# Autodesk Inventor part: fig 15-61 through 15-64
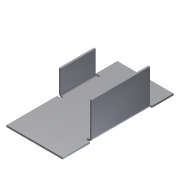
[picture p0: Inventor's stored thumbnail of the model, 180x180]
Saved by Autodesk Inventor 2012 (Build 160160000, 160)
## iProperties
Shininess: 77.0
Angle Display Precision: 2
Document Length Units: 11269
Document Angle Units: 11279
Document Time Units: 11290
Document Mass Units: 11283
Document Length Units Precision: 3
Document Angle Units Precision: 2
Compacted: True
Created: 2002-04
Part Number: fig 15-61 through 15-64
Document SubType Name: Sheet Metal
Density: 1 g/cm^3
Sheet Metal Rule: Default
Material: Default
Density: 0.0
Volumn: 0.0
Area: 0.0
PropertySet Name: Model Information
Control State: 0
Master: False
Checked Out: False
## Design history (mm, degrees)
node "Face1"
  sketch "Sketch1"
    geometry: L1 (-33.176, 5.765)-(14.235, 5.765); L2 (14.235, 5.765)-(14.235, -18.235); L3 (14.235, -18.235)-(-33.176, -18.235); L4 (-33.176, -18.235)-(-33.176, 5.765)
    constraints: 8 end point, 2 parallel, 1 horizontal, 1 perpendicular
node "Flange1"
node "Flange2"
body "Solid1"
face "Plate1" dims "Thickness" = 0.75
sketch "Sketch2"
  geometry: L1 (37.412, 0)-(22.412, 0); L2 (22.412, 0)-(22.412, 10); L3 (22.412, 10)-(37.412, 10); L4 (37.412, 10)-(37.412, 0)
  constraints: 8 end point
face "Plate2" dims "d1" = 10, "d2" = 15, "d4" = 10, "d5" = 90 deg, "d6" = 0.75 (= BendRadius), "Thickness" = 0.75, "MinimumRemnant" = 1.5 (= 2 x Thickness), "BendReliefWidth" = 0.75 (= Thickness)
bend "Bend1" dims "d3" = 0.75 (= BendRadius), "d4" = 10, "d5" = 90 deg, "d6" = 0.75 (= BendRadius), "d15" = 0.75 (= BendReliefWidth), "d16" = 0.375 (= BendReliefDepth), "d17" = 1.5 (= MinimumRemnant), "SeamGap" = 0.01, "Thickness" = 0.75, "MinimumRemnant" = 1.5 (= 2 x Thickness), "BendReliefWidth" = 0.75 (= Thickness)
sketch "Sketch3"
  geometry: L1 (10, 0)-(35, 0); L2 (35, 0)-(35, 15); L3 (35, 15)-(10, 15); L4 (10, 15)-(10, 0)
  constraints: 8 end point
face "Plate3" dims "d7" = 10, "d8" = 25, "d10" = 15, "d11" = 90 deg, "d12" = 0.75 (= BendRadius), "Thickness" = 0.75, "MinimumRemnant" = 1.5 (= 2 x Thickness), "BendReliefWidth" = 0.75 (= Thickness)
bend "Bend2" dims "d9" = 0.75 (= BendRadius), "d10" = 15, "d11" = 90 deg, "d12" = 0.75 (= BendRadius), "d18" = 0.75 (= BendReliefWidth), "d19" = 0.375 (= BendReliefDepth), "d20" = 1.5 (= MinimumRemnant), "SeamGap" = 0.01, "Thickness" = 0.75, "MinimumRemnant" = 1.5 (= 2 x Thickness), "BendReliefWidth" = 0.75 (= Thickness)
other parameters: "BendRadius" = 0.75 (= Thickness), "BendReliefDepth" = 0.375 (= 0.5 x Thickness), "CornerReliefSize" = 3 (= 4 x Thickness), "TransitionRadius" = 0.75 (= BendRadius), "d0" = 0.75 (= BendRadius), "d13" = 0.75 (= BendRadius), "JacobiRadiusSize" = 0.75 (= Thickness), "GapSize" = 0.75 (= Thickness)
